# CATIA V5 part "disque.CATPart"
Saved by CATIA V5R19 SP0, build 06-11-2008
Part number: disque
Publications: "excentricite_maneton", "extrusion_disque", "diam_maneton", "extrusion_maneton", "diam_disque", "diam_int_disque"
Material "Aluminium": density 2710 kg/m3, Young's modulus 7e+10 Pa, Poisson ratio 0.346, thermal expansion 2.36e-05 1/K
Bounding box of the stored display mesh (mm): x 0 to 55, y -100 to 100, z -99.803 to 99.803
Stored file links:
  C:\Users\rcousturie\Desktop\EU_thinkMotion\iao\IAO_MMS_Groupe1\vduret\vduret\vduret\CATIA_disque\disque.CATPart
  C:\Program Files\Dassault Systemes\B19\intel_a\startup\materials\French\Catalog.CATMaterial
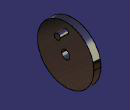
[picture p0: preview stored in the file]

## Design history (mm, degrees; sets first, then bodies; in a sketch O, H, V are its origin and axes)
Parameters
  excentricite_maneton = 70 mm
  extrusion_disque = 25 mm
  diam_maneton = 20 mm
  extrusion_maneton = 30 mm
  diam_disque = 200 mm
  diam_int_disque = 30 mm
Body1 (main body), material "Aluminium"
  Sketch1 on yz-plane, origin (0, 0, 0), H (0, 1, 0), V (0, 0, 1)
    circle A1 centre (0, 0) radius 100
    circle A2 centre (0, 0) radius 15
    radius A1 = 100 {= diam_disque /2}
    radius A2 = 15 {= diam_int_disque /2}
  Pad1: profile Sketch1, direction (1, 0, 0), length 25 {= extrusion_disque}
  Sketch2 on end face of Pad1, origin (25, 0, 0), H (0, 1, 0), V (0, 0, 1)
    circle A1 centre (0, 70) radius 10
    point P1 (0, 70)
    radius A1 = 10 {= diam_maneton /2}
    distance O P1 = 70 {= excentricite_maneton}
    coincidence: P1 V
  Pad2: profile Sketch2, direction (1, 0, 0), length 30 {= extrusion_maneton}
  Point1: type Center, Curve edge [face of Pad2 from Sketch2.A1 | end face of Pad2]
  Line1: type PtDir, RefPoint Point1, Direction end face of Pad2, Start -25, End 25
